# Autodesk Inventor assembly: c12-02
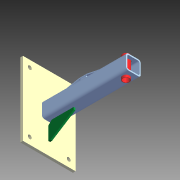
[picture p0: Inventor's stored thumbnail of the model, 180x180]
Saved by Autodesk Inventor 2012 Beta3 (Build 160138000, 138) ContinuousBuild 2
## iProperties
Created: 2011-01
Part Number: c12-02
Document SubType Name: Weldment
Designer: Beta-8540w
Weld Material: Welded Steel Mild
_SolveAssemblyDoc: Frame Generator Solve Assembly
_Version: 15.0.0
Author: Beta-8540w
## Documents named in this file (5)
- C:\Inventor 2012 Essentials\Assemblies\Chapter 12\c12-02.iam
- C:\Inventor 2012 Essentials\Parts\Chapter 12\c12-01.ipt
- C:\Inventor 2012 Essentials\Parts\Chapter 12\c12-02.ipt
- C:\Inventor 2012 Essentials\Assemblies\Chapter 12\Frame\Frame c12-01.iam
- C:\Inventor 2012 Essentials\Parts\Chapter 12\c12-03.ipt
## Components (4 placed, 4 different names)
1. c12-01:1 — Mate:2
2. c12-02:1 — Flush:1
3. Frame c12-01:1 [sub-assembly] — Mate:3
4. c12-03:1 — Mate:1, Mate:2, Mate:3
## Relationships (4: Mate 3, Flush 1)
- Flush:1: c12-02:1
- Mate:1: c12-03:1
- Mate:2: c12-01:1 ↔ c12-03:1
- Mate:3: Frame c12-01:1 ↔ c12-03:1
